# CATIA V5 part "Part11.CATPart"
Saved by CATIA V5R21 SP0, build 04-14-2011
Part number: Part1
Bounding box of the stored display mesh (mm): x 0 to 0, y -49.853 to 49.853, z -39.995 to 135.998
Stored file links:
  C:\Users\RIAD MAHAMUD PIASH\Desktop\Part11.CATPart
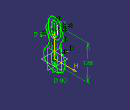
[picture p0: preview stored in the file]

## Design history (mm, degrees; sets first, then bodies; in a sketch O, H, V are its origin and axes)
Body1 (main body)
  Sketch1 on yz-plane, origin (0, 0, 0), H (0, 1, 0), V (0, 0, 1)
    arc A1 centre (0, 0) radius 40 from (-28.4873, 28.0797) to (40, 0) ccw
    arc A2 centre (0, 10) radius 12 from (11.9583, 9) to (-11.9583, 9) ccw
    point P1 (0, 10)
    arc A3 centre (0, -14) radius 10 from (-9.9652, -14.8333) to (9.9652, -14.8333) ccw
    point P2 (0, -14)
    line L1 (-11.9583, 9) -> (-9.9652, -14.8333)
    line L2 (11.9583, 9) -> (9.9652, -14.8333)
    arc A4 centre (0, 86) radius 32 from (-22, 109.2379) to (-25.7305, 66.9752) ccw
    point P7 (0, 86)
    axis line L3 (0, 86) -> (0, 114)
    point P8 (0, 114)
    construction line L4 (0, 114) -> (0, 86)
    line L5 (22, 114) -> (22, 86)
    line L6 (-22, 86) -> (-22, 114)
    arc A5 centre (0, 86) radius 22 from (22, 86) to (-22, 86) cw
    arc A6 centre (0, 114) radius 22 from (-22, 114) to (22, 114) cw
    construction line L7 (0, 86) -> (0, 114)
    line L8 (-12, 86) -> (-12, 98)
    line L9 (12, 98) -> (12, 86)
    arc A7 centre (0, 86) radius 12 from (12, 86) to (-12, 86) cw
    construction line L10 (0, 86) -> (0, 114)
    line L11 (-10, 100) -> (-10, 114)
    line L12 (10, 114) -> (10, 100)
    arc A8 centre (0, 114) radius 10 from (-10, 114) to (10, 114) cw
    point P17 (-22, 109.2379)
    point P18 (22, 109.2379)
    arc A9 centre (-10, 98) radius 2 from (-12, 98) to (-10, 100) cw
    arc A10 centre (10, 98) radius 2 from (10, 100) to (12, 98) cw
    arc A11 centre (-49.8528, 49.1395) radius 30 from (-25.7305, 66.9752) to (-28.4873, 28.0797) cw
    point P27 (-25.7305, 66.9752)
    point P28 (-28.4873, 28.0797)
    point P31 (25.7305, 66.9752)
    point P32 (22, 109.2379)
    arc A12 centre (0, 86) radius 32 from (22, 109.2379) to (25.7305, 66.9752) cw
    point P34 (28.4873, 28.0797)
    arc A13 centre (49.8528, 49.1395) radius 30 from (25.7305, 66.9752) to (28.4873, 28.0797) ccw
    arc A14 centre (0, 0) radius 40 from (40, 0) to (28.4873, 28.0797) ccw
    radius A3 = 10
    radius A2 = 12
    distance P1 H = 10
    distance P2 H = 14
    radius A1 = 40
    length L3 = 28
    distance P8 P2 = 128
    radius A4 = 32
    distance L4 L5 = 22
    distance L7 L8 = 12
    distance L10 L11 = 10
    radius A9 = 2
    radius A10 = 2
    radius A11 = 30
    coincidence: P1 V, P2 V, P7 V, L6 P17, L5 P18, A4 P18
    tangency: L1 A2, L1 A3, L2 A2, L2 A3, A5 L5, A6 L5, A5 L6, A6 L6, A7 L8, A7 L9, A8 L11, A8 L12, A9 L8, A10 L9, A11 A4, A11 A1, A14 A11
    vertical: L3 V, L4 V, L7 V, L10 V
    symmetry: P27 P31 V, P17 P32 V, A4 A12 V, P28 P34 V, A11 A13 V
